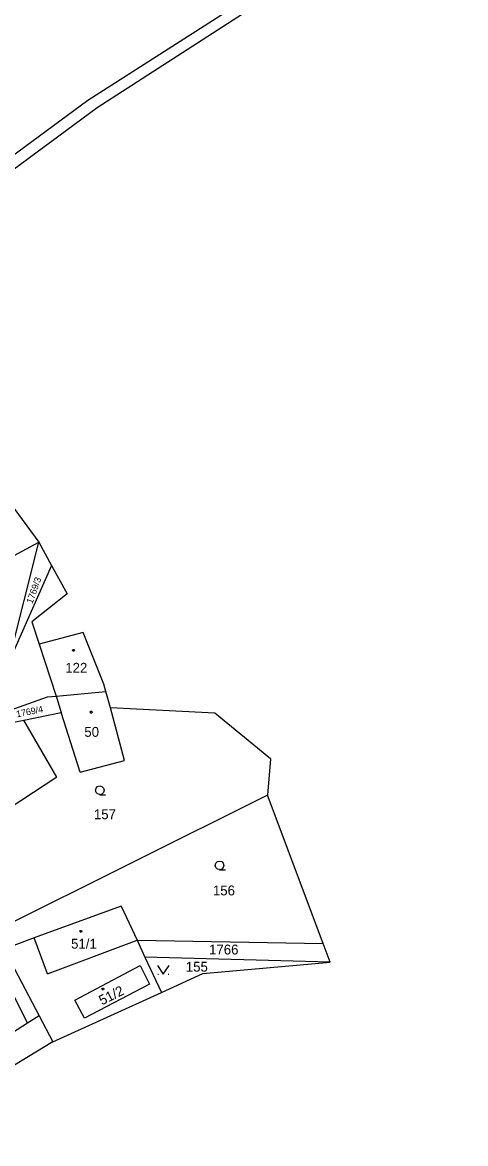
# Model space of a CAD drawing. Extents: x -799786 to -795190, y -1021716 to -1017834.
# Drawn here: x -797636.1 to -797559.9, y -1018901.4 to -1018708.6 of the extents above; entities that cross this region are included whole.
import ezdxf

# ---------------------------------------------------------------- set-up
doc = ezdxf.new("R2010")
doc.units = 0
for name, color, linetype in [('Default', 7, 'Continuous'), ('KN_HRANICE', 7, 'Continuous'), ('KN_KULTURY', 7, 'Continuous'), ('KN_PARCELY', 7, 'Continuous'), ('KN_SLUCKY', 7, 'Continuous')]:
    doc.layers.add(name, color=color, linetype=linetype)

# ---------------------------------------------------------------- blocks, each defined once
blk = doc.blocks.new('304')
at = {"layer": 'Default'}
blk.add_lwpolyline([(0, 0), (-0.38, 0.1), (-0.65, 0.37), (-0.75, 0.74), (-0.65, 1.11), (-0.38, 1.38), (-0.01, 1.48), (0.36, 1.38), (0.63, 1.11), (0.73, 0.73), (0.63, 0.35), (0.36, 0.08), (-0.02, -0.02), (0.98, -0.02)], dxfattribs=at)
blk = doc.blocks.new('314')
at = {"layer": 'Default'}
for p, q in [((-0.95, 0), (-0.85, 0)), ((0.85, 0), (0.95, 0))]:
    blk.add_line(p, q, dxfattribs=at)
blk.add_lwpolyline([(-1, 1.5), (0, 0), (1, 1.5)], dxfattribs=at)
blk = doc.blocks.new('NAHRADNI_SYMBOL')
at = {"layer": 'Default'}
blk.add_lwpolyline([(0.09, 0.15), (0.18, 0), (0.09, -0.15), (-0.09, -0.15), (-0.18, 0), (-0.09, 0.15), (0.09, 0.15)], dxfattribs=at)
blk = doc.blocks.new('402')
at = {"layer": 'Default'}
blk.add_lwpolyline([(0.09, 0.15), (0.18, 0), (0.09, -0.15), (-0.09, -0.15), (-0.18, 0), (-0.09, 0.15), (0.09, 0.15)], dxfattribs=at)

msp = doc.modelspace()

# ---------------------------------------------------------------- linework, layer by layer
at = {"layer": 'KN_HRANICE'}
for p, q in [((-797624.87, -1018722), (-797559.91, -1018680.44)), ((-797623.26, -1018723.28), (-797560.8, -1018682.93)), ((-797675.47, -1018759.21), (-797624.87, -1018722)), ((-797673.64, -1018760.45), (-797623.26, -1018723.28)), ((-797638.22, -1018791.29), (-797633.31, -1018798)), ((-797645.82, -1018804.79), (-797633.31, -1018798)), ((-797638.53, -1018818.79), (-797633.31, -1018798)), ((-797633.31, -1018798), (-797631.1, -1018802.05)), ((-797631.1, -1018802.05), (-797638.53, -1018818.79)), ((-797631.1, -1018802.05), (-797628.45, -1018806.92)), ((-797628.45, -1018806.92), (-797634.49, -1018811.72)), ((-797634.49, -1018811.72), (-797633.24, -1018815.55)), ((-797625.65, -1018813.56), (-797633.24, -1018815.55)), ((-797622.1, -1018822.41), (-797625.65, -1018813.56)), ((-797633.24, -1018815.55), (-797630.32, -1018824.47)), ((-797621.75, -1018823.7), (-797622.1, -1018822.41)), ((-797630.32, -1018824.47), (-797621.75, -1018823.7)), ((-797630.32, -1018824.47), (-797630.2, -1018824.83)), ((-797630.2, -1018824.83), (-797629.43, -1018827.3)), ((-797620.99, -1018826.51), (-797621.75, -1018823.7)), ((-797635.85, -1018828.6), (-797629.43, -1018827.3)), ((-797626.21, -1018837.54), (-797629.43, -1018827.3)), ((-797618.55, -1018835.55), (-797620.99, -1018826.51)), ((-797603.04, -1018827.4), (-797620.99, -1018826.51)), ((-797643.65, -1018830.18), (-797635.85, -1018828.6)), ((-797630.19, -1018838.4), (-797635.85, -1018828.6)), ((-797593.47, -1018835.25), (-797603.04, -1018827.4)), ((-797626.21, -1018837.54), (-797618.55, -1018835.55)), ((-797593.47, -1018835.25), (-797594, -1018841.5)), ((-797630.19, -1018838.4), (-797644.78, -1018847.97)), ((-797594, -1018841.5), (-797640.89, -1018864.9)), ((-797584.39, -1018867.02), (-797594, -1018841.5)), ((-797619.15, -1018860.6), (-797634.08, -1018866.08)), ((-797619.15, -1018860.6), (-797616.41, -1018866.47)), ((-797634.08, -1018866.08), (-797639.27, -1018867.99)), ((-797616.41, -1018866.47), (-797615.05, -1018869.38)), ((-797616.41, -1018866.47), (-797584.39, -1018867.02)), ((-797583.18, -1018870.25), (-797584.39, -1018867.02)), ((-797639.27, -1018867.99), (-797633.26, -1018879.48)), ((-797615.05, -1018869.38), (-797612.23, -1018875.43)), ((-797583.18, -1018870.25), (-797615.05, -1018869.38)), ((-797640.54, -1018870.29), (-797635.25, -1018880.75)), ((-797627.1, -1018876.75), (-797615.89, -1018870.82)), ((-797615.89, -1018870.82), (-797614.26, -1018874.05)), ((-797605.12, -1018872.18), (-797583.18, -1018870.25)), ((-797612.23, -1018875.43), (-797605.12, -1018872.18)), ((-797630.91, -1018883.96), (-797612.23, -1018875.43)), ((-797614.26, -1018874.05), (-797625.45, -1018879.89)), ((-797625.45, -1018879.89), (-797627.1, -1018876.75)), ((-797635.25, -1018880.75), (-797654.58, -1018893.08)), ((-797633.26, -1018879.48), (-797635.25, -1018880.75)), ((-797633.26, -1018879.48), (-797630.91, -1018883.96)), ((-797630.91, -1018883.96), (-797659.63, -1018901.44))]:
    msp.add_line(p, q, dxfattribs=at)
msp.add_lwpolyline([(-797643.65, -1018830.18), (-797638.25, -1018826.91), (-797631.8, -1018824.6), (-797630.32, -1018824.47)], dxfattribs=at)
at = {"layer": 'KN_SLUCKY'}
for q in [(-797634.08, -1018866.08), (-797616.41, -1018866.47)]:
    msp.add_line((-797631.78, -1018872.24), q, dxfattribs=at)

# ---------------------------------------------------------------- block references
at = {"layer": 'KN_KULTURY'}
for name, p in [('NAHRADNI_SYMBOL', (-797627.34, -1018816.62)), ('NAHRADNI_SYMBOL', (-797624.29, -1018827.25)), ('304', (-797622.8, -1018841.42)), ('304', (-797602.2, -1018854.33)), ('402', (-797626.06, -1018864.96)), ('314', (-797611.89, -1018872.29)), ('402', (-797622.27, -1018874.87))]:
    msp.add_blockref(name, p, dxfattribs=at)

# ---------------------------------------------------------------- texts
at = {"layer": 'KN_PARCELY'}
for s, height, rotation, p in [('1769/3', 1.14, 70.474, (-797634.4, -1018808.68)), ('1769/4', 1.14, 11.287, (-797637.06, -1018828.16)), ('51/2', 1.7, 26.299, (-797622.45, -1018877.69))]:
    msp.add_text(s, height=height, rotation=rotation, dxfattribs=at).set_placement(p)
for s, p in [('122', (-797628.75, -1018820.47)), ('50', (-797625.47, -1018831.49)), ('157', (-797623.83, -1018845.66)), ('156', (-797603.36, -1018858.76)), ('51/1', (-797627.75, -1018867.92)), ('1766', (-797604.02, -1018868.92)), ('155', (-797608.02, -1018871.88))]:
    msp.add_text(s, height=1.7, dxfattribs=at).set_placement(p)

doc.saveas('drawing.dxf')
